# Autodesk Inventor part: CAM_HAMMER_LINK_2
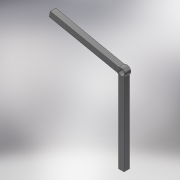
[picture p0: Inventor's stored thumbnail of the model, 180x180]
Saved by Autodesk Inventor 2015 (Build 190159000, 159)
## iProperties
Created: 2014-08
Part Number: CAM_HAMMER_LINK_2
Material: Steel, Mild
Document SubType Name: Modeling
Designer: lakshayg
Density: 7.85 g/cm^3
Appearance: Semi-Polished
Mass: 380.656 g
Surface Area: 171.083 cm^2
Volume: 48.4912 cm^3
Author: lakshayg
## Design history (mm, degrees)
sketch "Sketch1"
  geometry: L1 (154.2, 38.287)-(5.01, 7.174); L2 (156.65, 26.54)-(7.46, -4.573); L3 (6, -6.369)-(6, -184.169); L4 (154.2, 38.287)-(156.65, 26.54); L5 (6, -184.169)-(-6, -184.169); L6 (-6, -6.369)-(-6, -184.169); C1 r 6.25 at (0, 0); A1 r 8.75 centre (0, 0) between (7.46, -4.573) and (6, -6.369); 1 further point
  constraints: 12 end point, 4 point on circle, 3 parallel, 2 centre point, 2 coincident, 1 horizontal
  dimensions: "d1" = 12.5 diameter of C1; "d2" = 17.5 diameter of A1; "d15" = 152.4 distance of L1.start L1.end; "d16" = 101.78 deg angle of L3 L2; "d17" = 12 distance between parallel lines of L1 L2; "d18" = 12 distance between parallel lines of L6 L3; "d19" = 177.8 distance of L6.start L5.end
extrude "Extrusion1" new body sketch "Sketch1" distance "d6" = 12; taper "d7" = 0 deg
extrude "Extrusion2" join sketch "Sketch1" distance "d8" = 12; taper "d9" = 0 deg
extrude "Extrusion3" join sketch "Sketch1" distance "d11" = 12; taper "d12" = 0 deg
node "Midplane"
body "Solid1"
